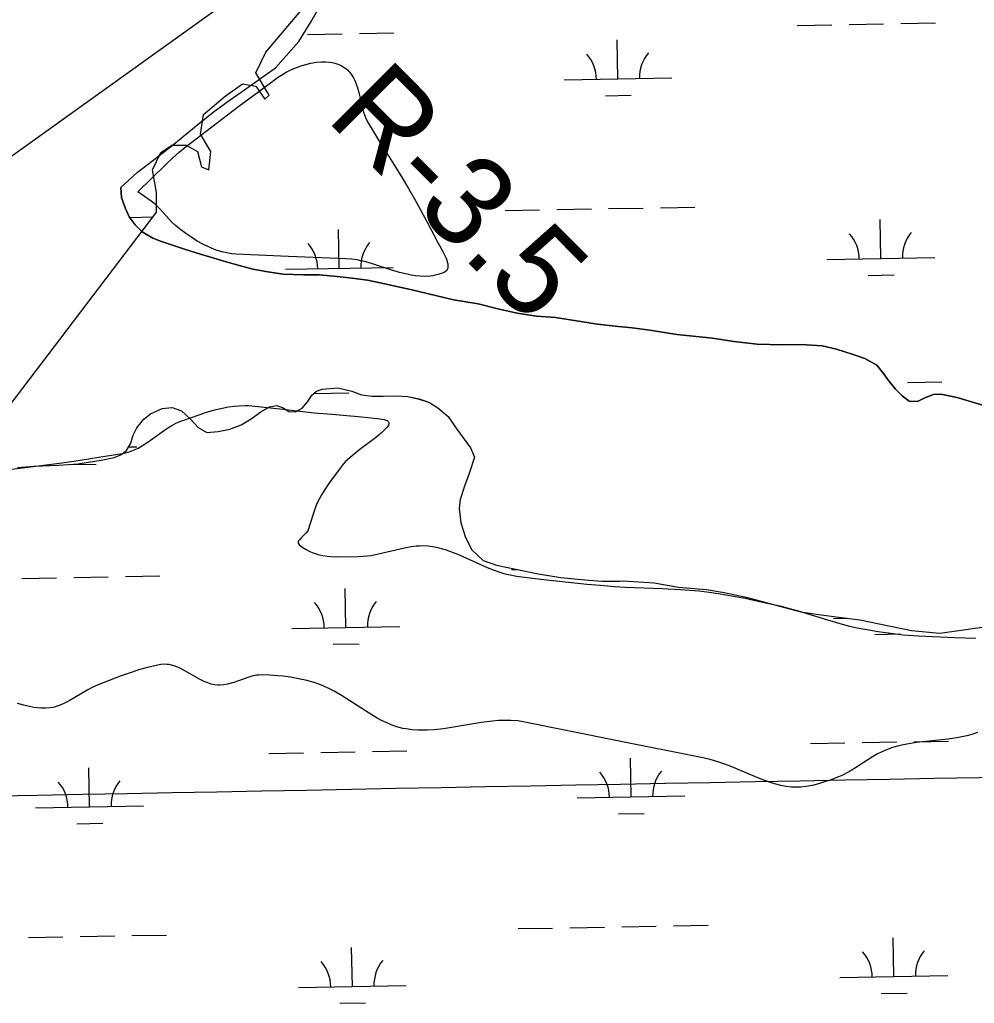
# Model space of a CAD drawing. Extents: x 3957609 to 3995875, y 234277 to 260273.
# Drawn here: x 3963753 to 3964638, y 242572 to 243483 of the extents above; entities that cross this region are included whole.
import ezdxf

# ---------------------------------------------------------------- set-up
doc = ezdxf.new("R2010")
doc.units = 0
for name, color, linetype in [('V-GRID-MAJR', 7, 'Continuous'), ('V-RIVR-EDGE', 7, 'Continuous'), ('V-RIVR-RANG-IDEN', 7, 'Continuous'), ('V-SITE-VEGE', 7, 'Continuous'), ('V-TOPO-MINR', 7, 'Continuous'), ('V-TOPO-SHOR', 7, 'Continuous'), ('V-WETL-SWMP', 7, 'Continuous')]:
    doc.layers.add(name, color=color, linetype=linetype)

msp = doc.modelspace()

# ---------------------------------------------------------------- linework, layer by layer
at = {"layer": 'V-GRID-MAJR'}
msp.add_spline([(3961816.723, 242728.005), (3967136.284, 242827.44), (3972455.83, 242927.648), (3977775.362, 243028.63), (3983094.879, 243130.385), (3988414.381, 243232.915), (3993733.868, 243336.218)], degree=3, dxfattribs=at)
at = {"layer": 'V-RIVR-EDGE'}
msp.add_line((3963687.931, 243051.661), (3963880.463, 243304.698), dxfattribs=at)
msp.add_lwpolyline([(3963880.363, 243304.782), (3963880.363, 243322.773), (3963876.575, 243343.604), (3963884.15, 243359.701), (3963894.566, 243366.329), (3963907.822, 243366.329), (3963918.237, 243360.647), (3963922.025, 243346.444), (3963928.653, 243343.604), (3963930.547, 243360.647), (3963921.078, 243376.744), (3963923.919, 243394.735), (3963943.803, 243411.778), (3963959.899, 243423.141), (3963972.209, 243421.247), (3963980.73, 243408.938), (3963984.518, 243412.725), (3963972.209, 243433.556), (3963981.677, 243452.493), (3964022.393, 243500.783)], dxfattribs=at)
at = {"layer": 'V-SITE-VEGE'}
msp.add_lwpolyline([(3963862.816, 243323.122), (3963888.924, 243348.671), (3963895.435, 243354.766), (3963901.317, 243359.884), (3963906.58, 243364.23), (3963956.617, 243402.745), (3963974.949, 243416.333), (3963993.419, 243429.631), (3963996.938, 243431.974), (3964000.526, 243434.061), (3964004.104, 243435.896), (3964007.618, 243437.489), (3964011.024, 243438.855), (3964014.299, 243440.008), (3964017.416, 243440.964), (3964023.341, 243442.402), (3964028.541, 243443.231), (3964033.04, 243443.59), (3964036.905, 243443.598), (3964040.202, 243443.352), (3964043.006, 243442.937), (3964045.385, 243442.406), (3964047.403, 243441.812), (3964050.77, 243440.469), (3964053.137, 243439.193), (3964054.818, 243438.079), (3964057.17, 243436.147), (3964059.297, 243433.891), (3964061.206, 243431.341), (3964062.736, 243428.834), (3964063.979, 243426.389), (3964064.991, 243424.029), (3964066.566, 243419.458), (3964067.686, 243415.342), (3964071.022, 243400.69), (3964072.018, 243397.11), (3964072.88, 243394.483), (3964074.422, 243390.663), (3964076.335, 243387.02), (3964085.645, 243371.861), (3964106.93, 243337.794), (3964113.817, 243326.303), (3964120.887, 243313.908), (3964131.084, 243295.104), (3964141.076, 243276.235), (3964145.639, 243267.912), (3964147.13, 243264.957), (3964148.297, 243262.36), (3964149.158, 243260.124), (3964149.743, 243258.225), (3964150.106, 243256.63), (3964150.286, 243255.295), (3964150.327, 243254.185), (3964150.11, 243252.395), (3964149.676, 243251.199), (3964149.184, 243250.394), (3964148.158, 243249.355), (3964146.755, 243248.54), (3964144.015, 243247.457), (3964141.353, 243246.605), (3964138.764, 243245.952), (3964136.245, 243245.475), (3964133.798, 243245.151), (3964129.036, 243244.879), (3964124.549, 243245.012), (3964120.324, 243245.438), (3964116.347, 243246.064), (3964112.609, 243246.826), (3964105.57, 243248.622), (3964099.387, 243250.474), (3964080.365, 243256.583), (3964074.24, 243258.313), (3964069.646, 243259.426), (3964066.201, 243260.124), (3964061.042, 243260.908), (3964055.89, 243261.324), (3964002.506, 243263.454), (3963953.668, 243265.584), (3963950.11, 243265.869), (3963946.811, 243266.331), (3963943.751, 243266.927), (3963940.907, 243267.624), (3963935.647, 243269.256), (3963931.121, 243271.007), (3963927.218, 243272.758), (3963923.847, 243274.441), (3963918.049, 243277.688), (3963913.785, 243280.334), (3963907.52, 243284.565), (3963901.419, 243289.019), (3963897.821, 243292.009), (3963894.909, 243294.825), (3963884.046, 243306.855), (3963879.884, 243310.953), (3963877.656, 243312.839), (3963875.295, 243314.584)], close=True, dxfattribs=at)
for points in [[(3963803.494, 243073.834), (3963826.935, 243077.315), (3963838.632, 243079.234), (3963850.307, 243081.299), (3963853.998, 243082.165), (3963857.338, 243083.269), (3963860.375, 243084.528), (3963863.154, 243085.886), (3963868.217, 243088.807), (3963872.536, 243091.666), (3963887.501, 243102.432), (3963891.355, 243104.965), (3963894.319, 243106.739), (3963898.9, 243109.135), (3963901.268, 243110.188), (3963903.69, 243111.126), (3963919.708, 243116.801), (3963925.737, 243118.789), (3963931.027, 243120.393), (3963935.666, 243121.665), (3963939.731, 243122.658), (3963946.866, 243124.065), (3963952.234, 243124.802), (3963956.271, 243125.15), (3963962.341, 243125.306), (3963965.384, 243125.204), (3963968.432, 243124.972), (3963997.395, 243121.841), (3964026.359, 243118.582), (3964042.59, 243117.145), (3964066.992, 243115.265), (3964079.106, 243113.983), (3964085.123, 243113.163), (3964091.101, 243112.191), (3964092.711, 243111.812), (3964093.915, 243111.328), (3964094.765, 243110.763), (3964095.303, 243110.124), (3964095.576, 243109.428), (3964095.613, 243108.68), (3964095.451, 243107.89), (3964095.117, 243107.067), (3964094.034, 243105.354), (3964092.504, 243103.556), (3964090.685, 243101.738), (3964088.684, 243099.931), (3964084.451, 243096.431), (3964068.786, 243084.5), (3964063.498, 243080.34), (3964059.805, 243077.256), (3964057.27, 243074.983), (3964055.525, 243073.309), (3964053.221, 243070.864), (3964051.347, 243068.515), (3964040.65, 243053.946), (3964035.524, 243046.487), (3964033.134, 243042.641), (3964030.902, 243038.688), (3964029.229, 243035.249), (3964027.953, 243032.163), (3964026.026, 243026.644), (3964022.143, 243014.051), (3964020.68, 243009.928), (3964020.226, 243008.998), (3964018.929, 243007.263), (3964017.479, 243005.758), (3964014.735, 243003.172), (3964012.935, 243001.287), (3964011.976, 242999.915), (3964011.577, 242998.916), (3964011.505, 242998.183), (3964011.593, 242997.642), (3964011.989, 242996.849), (3964012.73, 242996.079), (3964015.913, 242993.689)], [(3963728.775, 243064.255), (3963787.837, 243071.712), (3963803.494, 243073.834)], [(3964015.913, 242993.689), (3964018.946, 242991.785), (3964021.829, 242990.265), (3964024.563, 242989.063), (3964027.152, 242988.111), (3964029.599, 242987.363), (3964034.234, 242986.3), (3964038.328, 242985.684), (3964041.93, 242985.344), (3964048.271, 242985.098), (3964067.248, 242985.428), (3964071.438, 242985.587), (3964075.366, 242985.968), (3964079.052, 242986.495), (3964085.969, 242987.828), (3964110.168, 242993.597), (3964116.205, 242994.67), (3964120.729, 242995.223), (3964124.119, 242995.459), (3964129.194, 242995.473), (3964131.729, 242995.307), (3964134.26, 242995.014), (3964139.397, 242994.097), (3964144.146, 242992.932), (3964148.547, 242991.609), (3964152.641, 242990.193), (3964160.237, 242987.191), (3964186.572, 242975.362), (3964193.226, 242972.695), (3964198.267, 242970.928), (3964202.084, 242969.76), (3964207.878, 242968.321), (3964213.77, 242967.319), (3964236.419, 242964.503), (3964253.44, 242962.531), (3964279.013, 242959.887), (3964291.819, 242958.742), (3964304.634, 242957.733), (3964314.425, 242957.11), (3964348.733, 242955.676), (3964365.883, 242954.829), (3964374.45, 242954.233), (3964383.004, 242953.471), (3964392.476, 242952.379), (3964400.732, 242951.218), (3964415.117, 242948.789), (3964425.865, 242946.7), (3964441.936, 242943.266), (3964457.969, 242939.622), (3964466.991, 242937.361), (3964474.814, 242935.143), (3964501.993, 242926.681), (3964515.659, 242922.702), (3964522.561, 242920.936), (3964529.524, 242919.384), (3964536.576, 242918.008), (3964548.948, 242915.906), (3964558.256, 242914.585), (3964572.26, 242913.012), (3964586.313, 242911.927), (3964599.66, 242911.22), (3964619.679, 242910.424), (3964639.701, 242909.795)], [(3963855.003, 242877.484), (3963847.567, 242874.87), (3963836.424, 242870.629), (3963825.32, 242866.121), (3963820.55, 242863.934), (3963816.505, 242861.796), (3963799.451, 242851.759), (3963794.286, 242849.123), (3963791.653, 242847.968), (3963788.972, 242846.948), (3963786.453, 242846.178), (3963784.028, 242845.635), (3963781.709, 242845.275), (3963777.265, 242844.941), (3963773.298, 242844.994), (3963769.79, 242845.275), (3963766.708, 242845.674), (3963761.32, 242846.678), (3963757.318, 242847.64), (3963751.446, 242849.332)], [(3964626.438, 242818.297), (3964622.049, 242817.475), (3964613.742, 242816.253), (3964584.564, 242813.101), (3964577.409, 242812.038), (3964572.117, 242811.032), (3964568.201, 242810.131), (3964562.426, 242808.499), (3964556.785, 242806.469), (3964553.851, 242805.2), (3964548.493, 242802.488), (3964543.92, 242799.84), (3964528.132, 242789.717), (3964524.097, 242787.255), (3964517.871, 242783.835), (3964514.654, 242782.297), (3964511.352, 242780.902), (3964505.507, 242778.682), (3964500.31, 242776.861), (3964495.716, 242775.411), (3964491.671, 242774.285), (3964488.126, 242773.431), (3964481.921, 242772.284), (3964477.286, 242771.768), (3964473.833, 242771.594), (3964468.701, 242771.727), (3964466.163, 242771.985), (3964463.648, 242772.38), (3964458.789, 242773.421), (3964454.26, 242774.613), (3964450.033, 242775.897), (3964442.146, 242778.653), (3964435.269, 242781.351), (3964411.144, 242791.363), (3964405.045, 242793.665), (3964400.439, 242795.252), (3964393.47, 242797.348), (3964386.412, 242799.013), (3964305.77, 242814.991), (3964221.718, 242832.035), (3964218.333, 242832.635), (3964215.044, 242833.073), (3964208.642, 242833.558), (3964202.612, 242833.624), (3964196.939, 242833.39), (3964191.604, 242832.954), (3964181.571, 242831.693), (3964146.356, 242825.874), (3964137.586, 242824.893), (3964131.033, 242824.484), (3964126.134, 242824.406), (3964122.47, 242824.494), (3964116.996, 242824.891), (3964111.546, 242825.643), (3964108.57, 242826.233), (3964102.932, 242827.738), (3964097.783, 242829.548), (3964093.059, 242831.547), (3964088.709, 242833.65), (3964084.684, 242835.795), (3964077.254, 242840.167), (3964051.533, 242856.713), (3964044.945, 242860.532), (3964039.907, 242863.164), (3964036.059, 242864.975), (3964030.163, 242867.369), (3964027.148, 242868.403), (3964024.086, 242869.316), (3964018.325, 242870.799), (3964013.242, 242871.936), (3964004.286, 242873.564), (3963997.548, 242874.485), (3963992.504, 242875.008), (3963984.971, 242875.522), (3963977.519, 242875.708), (3963975.094, 242875.614), (3963972.819, 242875.35), (3963968.544, 242874.477), (3963964.805, 242873.404), (3963951.765, 242868.827), (3963946.107, 242867.17), (3963942.494, 242866.453), (3963938.902, 242866.121), (3963937.185, 242866.138), (3963933.864, 242866.527), (3963930.757, 242867.272), (3963927.849, 242868.255), (3963925.125, 242869.386), (3963920.025, 242871.921), (3963904.444, 242880.713), (3963901.941, 242881.946), (3963897.559, 242883.773), (3963894.268, 242884.785), (3963891.802, 242885.303), (3963889.948, 242885.53), (3963887.167, 242885.6), (3963884.382, 242885.297), (3963877.027, 242883.794), (3963870.574, 242882.202), (3963864.918, 242880.619), (3963855.003, 242877.484)], [(3964641.124, 242822.376), (3964635.977, 242820.668), (3964631.081, 242819.339), (3964626.438, 242818.297)]]:
    msp.add_lwpolyline(points, dxfattribs=at)
at = {"layer": 'V-TOPO-MINR'}
msp.add_lwpolyline([(3963060.899, 242865.926), (3964240.98, 243711.482)], dxfattribs=at)
at = {"layer": 'V-TOPO-SHOR'}
for points in [[(3963847.182, 243327.104), (3963847.876, 243317.923), (3963851.268, 243308.283), (3963854.962, 243300.23), (3963860.555, 243292.665), (3963867.093, 243286.213), (3963876.792, 243280.418), (3963884.73, 243277.302), (3963906.318, 243270.159), (3963920.92, 243265.506), (3963932.506, 243262.096), (3963944.884, 243258.377), (3963958.053, 243254.822), (3963969.636, 243251.729), (3963983.272, 243249.286), (3963997.7, 243247.004), (3964016.55, 243246.496), (3964030.963, 243246.433), (3964047.603, 243244.801), (3964061.71, 243243.31), (3964075.661, 243241.344), (3964091.838, 243237.965), (3964107.065, 243234.741), (3964115.63, 243232.896), (3964155.605, 243223.34), (3964178.438, 243219.373), (3964196.524, 243214.9), (3964214.448, 243210.74), (3964232.519, 243208.166), (3964249.952, 243206.7), (3964269.453, 243203.661), (3964288.794, 243200.779), (3964305.279, 243198.827), (3964321.128, 243197.191), (3964337.297, 243195.079), (3964362.346, 243191.127), (3964395.473, 243187.545), (3964415.131, 243184.665), (3964437.004, 243182.275), (3964460.132, 243181.636), (3964477.552, 243181.909), (3964497.201, 243180.455), (3964510.367, 243177.374), (3964525.762, 243172.566), (3964536.715, 243168.836), (3964547.684, 243162.731), (3964554.072, 243154.855), (3964558.704, 243148.551), (3964565.094, 243140.515), (3964571.312, 243134.221), (3964577.839, 243129.355), (3964585.601, 243129.089), (3964592.23, 243132.46), (3964600.287, 243135.522), (3964607.254, 243135.884), (3964619.151, 243133.271), (3964623.274, 243132.505), (3964659.456, 243121.499)], [(3963751.354, 243067.899), (3963766.71, 243069.109), (3963789.508, 243070.051), (3963807.24, 243071.278), (3963829.076, 243074.587), (3963840.936, 243077.201), (3963847.098, 243079.46), (3963852.298, 243083.769), (3963856.216, 243089.814), (3963859.011, 243098.385), (3963861.979, 243104.58), (3963868.577, 243112.545), (3963874.721, 243117.653), (3963885.617, 243122.633), (3963894.638, 243123.485), (3963903.531, 243120.219), (3963911.34, 243112.826), (3963918.835, 243104.955), (3963926.786, 243100.257), (3963937.392, 243101.119), (3963948.304, 243103.409), (3963958.573, 243107.435), (3963967.883, 243112.883), (3963976.865, 243119.594), (3963984.914, 243123.924), (3963991.715, 243125.234), (3963997.749, 243123.215), (3964002.998, 243119.609), (3964009.019, 243119.33), (3964015.173, 243122.697), (3964020.359, 243128.909), (3964024.121, 243134.952), (3964028.53, 243138.624), (3964033.902, 243140.56), (3964048.148, 243141.762), (3964061.317, 243138.524), (3964070.209, 243135.098), (3964080.193, 243134.055), (3964090.171, 243133.963), (3964102.84, 243134.362), (3964113.297, 243133.639), (3964123.609, 243131.331), (3964133.292, 243128.071), (3964140.925, 243123.211), (3964150.64, 243115.039), (3964158.636, 243103.53), (3964171.104, 243086.189), (3964174.962, 243077.346), (3964170.305, 243063.219), (3964165.636, 243050.677), (3964161.601, 243038.137), (3964160.704, 243029.896), (3964162.377, 243016.602), (3964166.586, 243003.01), (3964172.521, 242991.486), (3964183.038, 242981.735), (3964195.422, 242977.383), (3964213.184, 242973.699), (3964233.803, 242969.242), (3964254.89, 242966.056), (3964277.078, 242963.668), (3964292.923, 242962.504), (3964309.395, 242962.615), (3964312.719, 242962.793), (3964341.559, 242960.925), (3964363.915, 242957.112), (3964390.064, 242954.753), (3964406.395, 242952.008), (3964426.854, 242947.71), (3964440.658, 242943.999), (3964462.235, 242938.281), (3964477.309, 242934.262), (3964493.957, 242931.68), (3964512.503, 242929.267), (3964532, 242926.863), (3964579.897, 242916.725), (3964606.046, 242914.522), (3964625.825, 242917.186), (3964649.877, 242920.512)]]:
    msp.add_lwpolyline(points, dxfattribs=at)
at = {"layer": 'V-WETL-SWMP'}
for p, q in [((3964522.111, 243478.262), (3964554.106, 243478.844)), ((3964570.104, 243479.134), (3964602.098, 243479.716)), ((3964020.286, 243469.137), (3964052.281, 243469.719)), ((3964068.279, 243470.01), (3964100.273, 243470.591)), ((3964474.119, 243477.389), (3964506.114, 243477.971)), ((3964307.927, 243427.93), (3964307.273, 243463.924)), ((3964257.935, 243427.021), (3964357.919, 243428.839)), ((3964296.21, 243412.283), (3964320.206, 243412.719)), ((3964203.284, 243305.936), (3964235.278, 243306.518)), ((3964251.276, 243306.809), (3964283.27, 243307.39)), ((3964299.268, 243307.681), (3964331.263, 243308.263)), ((3964347.26, 243308.554), (3964379.255, 243309.136)), ((3963855.421, 243299.611), (3963877.43, 243300.011)), ((3964551.465, 243261.517), (3964550.81, 243297.511)), ((3964049.64, 243252.392), (3964048.985, 243288.386)), ((3964501.473, 243260.608), (3964601.457, 243262.426)), ((3963999.648, 243251.483), (3964099.631, 243253.301)), ((3964539.747, 243245.87), (3964563.743, 243246.306)), ((3964033.903, 243140.56), (3964048.149, 243141.762)), ((3964048.149, 243141.762), (3964061.317, 243138.523)), ((3964576.152, 243146.514), (3964608.146, 243147.096)), ((3964020.359, 243128.908), (3964024.12, 243134.952)), ((3964024.12, 243134.952), (3964028.531, 243138.624)), ((3964026.334, 243136.517), (3964058.329, 243137.099)), ((3964028.531, 243138.624), (3964033.903, 243140.56)), ((3964061.317, 243138.523), (3964070.209, 243135.098)), ((3964070.209, 243135.098), (3964080.193, 243134.055)), ((3964080.193, 243134.055), (3964090.172, 243133.962)), ((3964090.172, 243133.962), (3964102.84, 243134.363)), ((3964102.84, 243134.363), (3964113.298, 243133.64)), ((3964113.298, 243133.64), (3964123.608, 243131.332)), ((3963885.617, 243122.634), (3963894.639, 243123.486)), ((3963894.639, 243123.486), (3963903.53, 243120.219)), ((3963976.865, 243119.594), (3963984.914, 243123.923)), ((3963984.914, 243123.923), (3963991.716, 243125.235)), ((3963991.716, 243125.235), (3963997.748, 243123.216)), ((3963997.748, 243123.216), (3964002.998, 243119.608)), ((3964015.173, 243122.697), (3964020.359, 243128.908)), ((3964123.608, 243131.332), (3964133.291, 243128.07)), ((3964133.291, 243128.07), (3964140.925, 243123.21)), ((3964140.925, 243123.21), (3964150.641, 243115.039)), ((3963868.578, 243112.544), (3963874.722, 243117.653)), ((3963874.722, 243117.653), (3963885.617, 243122.634)), ((3963903.53, 243120.219), (3963911.34, 243112.826)), ((3963967.882, 243112.882), (3963976.865, 243119.594)), ((3964002.998, 243119.608), (3964009.019, 243119.331)), ((3964009.019, 243119.331), (3964015.173, 243122.697)), ((3964150.641, 243115.039), (3964158.636, 243103.529)), ((3963861.979, 243104.581), (3963868.578, 243112.544)), ((3963911.34, 243112.826), (3963918.836, 243104.956)), ((3963918.836, 243104.956), (3963926.786, 243100.257)), ((3963948.305, 243103.409), (3963958.573, 243107.436)), ((3963958.573, 243107.436), (3963967.882, 243112.882)), ((3963856.216, 243089.814), (3963859.011, 243098.385)), ((3963859.011, 243098.385), (3963861.979, 243104.581)), ((3963926.786, 243100.257), (3963937.392, 243101.119)), ((3963937.392, 243101.119), (3963948.305, 243103.409)), ((3964158.636, 243103.529), (3964171.104, 243086.19)), ((3963852.297, 243083.769), (3963856.216, 243089.814)), ((3963854.361, 243086.952), (3963862.142, 243087.094)), ((3963840.936, 243077.201), (3963847.098, 243079.459)), ((3963847.098, 243079.459), (3963852.297, 243083.769)), ((3964171.104, 243086.19), (3964174.963, 243077.346)), ((3963751.353, 243067.899), (3963766.709, 243069.109)), ((3963766.709, 243069.109), (3963789.509, 243070.051)), ((3963789.509, 243070.051), (3963807.24, 243071.277)), ((3963800.433, 243070.538), (3963824.429, 243070.975)), ((3963807.24, 243071.277), (3963829.075, 243074.588)), ((3963829.075, 243074.588), (3963840.936, 243077.201)), ((3964174.963, 243077.346), (3964170.305, 243063.219)), ((3964170.305, 243063.219), (3964165.636, 243050.676)), ((3964165.636, 243050.676), (3964161.601, 243038.137)), ((3964161.601, 243038.137), (3964160.705, 243029.895)), ((3964160.705, 243029.895), (3964162.377, 243016.602)), ((3964162.377, 243016.602), (3964166.585, 243003.009)), ((3964166.585, 243003.009), (3964172.521, 242991.486)), ((3964172.521, 242991.486), (3964183.038, 242981.736)), ((3964183.038, 242981.736), (3964195.421, 242977.383)), ((3964195.421, 242977.383), (3964213.184, 242973.699)), ((3964209.332, 242973.316), (3964214.52, 242973.41)), ((3964213.184, 242973.699), (3964233.803, 242969.242)), ((3964233.803, 242969.242), (3964254.889, 242966.055)), ((3963755.499, 242965.064), (3963787.493, 242965.646)), ((3963803.491, 242965.937), (3963835.486, 242966.518)), ((3963851.483, 242966.809), (3963883.478, 242967.391)), ((3964254.889, 242966.055), (3964277.078, 242963.668)), ((3964277.078, 242963.668), (3964292.924, 242962.505)), ((3964292.924, 242962.505), (3964309.395, 242962.614)), ((3964309.395, 242962.614), (3964312.72, 242962.794)), ((3964312.72, 242962.794), (3964341.558, 242960.925)), ((3964341.558, 242960.925), (3964363.915, 242957.113)), ((3964055.688, 242919.772), (3964055.033, 242955.766)), ((3964363.915, 242957.113), (3964390.063, 242954.752)), ((3964390.063, 242954.752), (3964406.395, 242952.009)), ((3964406.395, 242952.009), (3964426.855, 242947.709)), ((3964426.855, 242947.709), (3964440.658, 242943.999)), ((3964440.658, 242943.999), (3964462.236, 242938.281)), ((3964462.236, 242938.281), (3964477.309, 242934.263)), ((3964477.309, 242934.263), (3964493.956, 242931.68)), ((3964493.956, 242931.68), (3964512.503, 242929.268)), ((3964507.521, 242927.988), (3964520.91, 242928.231)), ((3964512.503, 242929.268), (3964532, 242926.863)), ((3964532, 242926.863), (3964579.898, 242916.726)), ((3964005.696, 242918.863), (3964105.68, 242920.681)), ((3964545.795, 242913.25), (3964569.791, 242913.686)), ((3964579.898, 242916.726), (3964606.045, 242914.522)), ((3964606.045, 242914.522), (3964625.826, 242917.187)), ((3964625.826, 242917.187), (3964649.878, 242920.513)), ((3964043.97, 242904.125), (3964067.966, 242904.562)), ((3964534.208, 242813.022), (3964566.202, 242813.604)), ((3964582.2, 242813.894), (3964614.194, 242814.476)), ((3964032.383, 242803.897), (3964064.377, 242804.479)), ((3964080.375, 242804.77), (3964112.369, 242805.351)), ((3964486.216, 242812.149), (3964518.21, 242812.731)), ((3963984.39, 242803.024), (3964016.385, 242803.606)), ((3964320.023, 242762.69), (3964319.369, 242798.684)), ((3963818.198, 242753.565), (3963817.544, 242789.559)), ((3964270.032, 242761.781), (3964370.015, 242763.599)), ((3963768.206, 242752.656), (3963868.19, 242754.474)), ((3964308.306, 242747.043), (3964332.302, 242747.479)), ((3963806.481, 242737.918), (3963830.477, 242738.355)), ((3964215.38, 242640.696), (3964247.375, 242641.278)), ((3964263.372, 242641.569), (3964295.367, 242642.15)), ((3964311.364, 242642.441), (3964343.359, 242643.023)), ((3964359.356, 242643.314), (3964391.351, 242643.896)), ((3963761.547, 242632.444), (3963793.542, 242633.026)), ((3963809.539, 242633.317), (3963841.534, 242633.898)), ((3963857.531, 242634.189), (3963889.526, 242634.771)), ((3964563.561, 242596.277), (3964562.906, 242632.271)), ((3964061.736, 242587.152), (3964061.081, 242623.146)), ((3964513.569, 242595.368), (3964613.553, 242597.186)), ((3964011.744, 242586.243), (3964111.728, 242588.061)), ((3964551.843, 242580.63), (3964575.839, 242581.066)), ((3964050.018, 242571.505), (3964074.014, 242571.942))]:
    msp.add_line(p, q, dxfattribs=at)
for points in [[(3963867.092, 243286.214), (3963860.556, 243292.665), (3963854.963, 243300.23), (3963851.267, 243308.283), (3963847.877, 243317.922), (3963847.183, 243327.104), (3963862.3, 243341.091), (3963882.037, 243356.431), (3963897.992, 243368.769), (3963915.586, 243383.103), (3963932.687, 243397.103), (3963947.494, 243407.946), (3963961.813, 243417.629), (3963990.61, 243437.988), (3964012.104, 243462.597), (3964023.72, 243481.025), (3964034.507, 243499.942)], [(3964659.456, 243121.499), (3964623.273, 243132.505), (3964619.15, 243133.27), (3964607.254, 243135.884), (3964600.287, 243135.521), (3964592.23, 243132.459), (3964585.6, 243129.089), (3964577.838, 243129.354), (3964571.312, 243134.221), (3964565.094, 243140.515), (3964558.705, 243148.551), (3964554.071, 243154.855), (3964547.683, 243162.732), (3964536.715, 243168.837), (3964525.762, 243172.566), (3964510.367, 243177.374), (3964497.201, 243180.455), (3964477.552, 243181.909), (3964460.132, 243181.636), (3964437.004, 243182.275), (3964415.131, 243184.665), (3964395.473, 243187.544), (3964362.347, 243191.127), (3964337.297, 243195.08), (3964321.128, 243197.19), (3964305.279, 243198.828), (3964288.794, 243200.778), (3964269.453, 243203.66), (3964249.951, 243206.699), (3964232.52, 243208.167), (3964214.447, 243210.741), (3964196.523, 243214.899), (3964178.437, 243219.372), (3964155.604, 243223.34), (3964115.629, 243232.896), (3964107.064, 243234.74), (3964091.838, 243237.965), (3964075.661, 243241.343), (3964061.71, 243243.31), (3964047.604, 243244.801), (3964030.963, 243246.433), (3964016.55, 243246.496), (3963997.699, 243247.005), (3963983.272, 243249.286), (3963969.635, 243251.73), (3963958.052, 243254.821), (3963944.883, 243258.377), (3963932.505, 243262.097), (3963920.92, 243265.505), (3963906.319, 243270.16), (3963884.731, 243277.303), (3963876.792, 243280.418), (3963867.092, 243286.214)]]:
    msp.add_lwpolyline(points, dxfattribs=at)
for centre, start, end in [((3964363.152, 243429.409), 140.269876, 181.813534), ((3964252.685, 243427.4), 0.269879, 41.813537), ((3964496.222, 243260.987), 0.269879, 41.813537), ((3964606.69, 243262.996), 140.269876, 181.813534), ((3963994.397, 243251.862), 0.269879, 41.813537), ((3964104.865, 243253.871), 140.269876, 181.813534), ((3964000.445, 242919.242), 0.269879, 41.813537), ((3964110.913, 242921.251), 140.269876, 181.813534), ((3964375.248, 242764.169), 140.269876, 181.813534), ((3963873.423, 242755.044), 140.269876, 181.813534), ((3964264.781, 242762.16), 0.269879, 41.813537), ((3963762.956, 242753.035), 0.269879, 41.813537), ((3964508.318, 242595.747), 0.269879, 41.813537), ((3964618.786, 242597.756), 140.269876, 181.813534), ((3964006.493, 242586.622), 0.269879, 41.813537), ((3964116.961, 242588.631), 140.269876, 181.813534)]:
    msp.add_arc(centre, 35.246, start, end, dxfattribs=at)

# ---------------------------------------------------------------- texts
at = {"layer": 'V-RIVR-RANG-IDEN'}
msp.add_text('R-3.5', height=83, rotation=314.903535, dxfattribs=at).set_placement((3964036.199, 243390.691))

doc.saveas('drawing.dxf')
